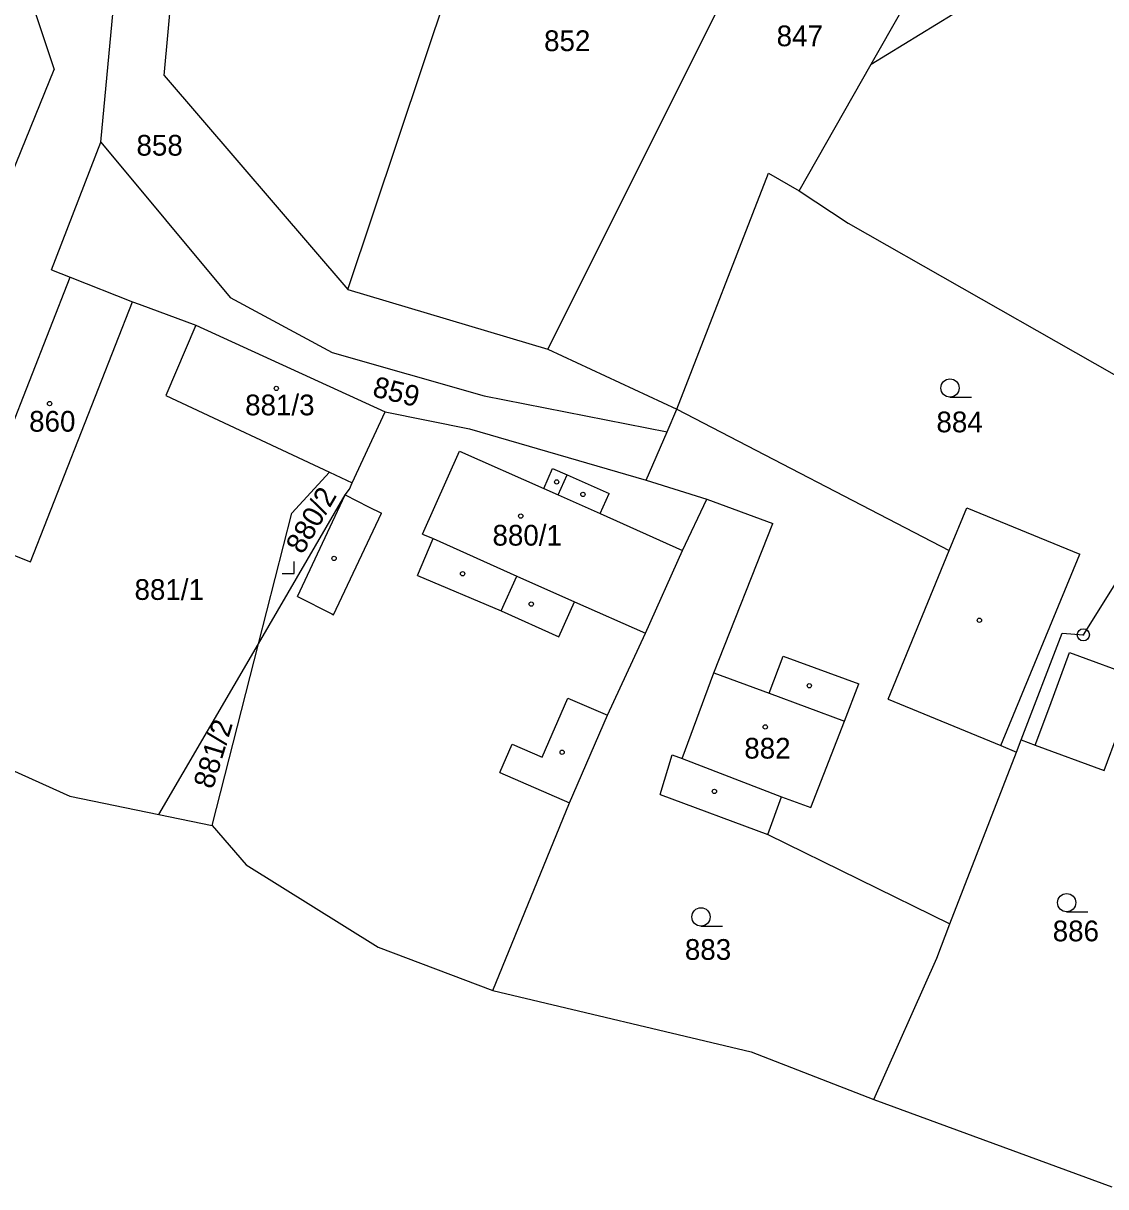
# Model space of a CAD drawing. Extents: x -779596 to -776743, y -1030330 to -1024513.
# Drawn here: x -777792.7 to -777704, y -1025546 to -1025450.6 of the extents above; entities that cross this region are included whole.
import ezdxf

# ---------------------------------------------------------------- set-up
doc = ezdxf.new("R2010")
doc.units = 0
for name, color, linetype in [('hranice parcel', 7, 'Continuous'), ('hranice vnitřní', 7, 'Continuous'), ('kultura', 7, 'Continuous'), ('Kód', 7, 'Continuous'), ('č_pacel stav_', 7, 'Continuous'), ('č_parcel poz_', 7, 'Continuous')]:
    doc.layers.add(name, color=color, linetype=linetype)

msp = doc.modelspace()

# ---------------------------------------------------------------- linework, layer by layer
at = {"layer": 'hranice parcel'}
for points in [[(-777786.38, -1025460.37), (-777782.85, -1025422.71)], [(-777766.12, -1025472.43), (-777751.71, -1025429.33)], [(-777781.19, -1025454.9), (-777779.17, -1025432.78)], [(-777723.23, -1025453.98), (-777712.96, -1025435.94)], [(-777723.23, -1025453.98), (-777697.79, -1025438.36)], [(-777793.53, -1025444.4), (-777790.21, -1025454.41)], [(-777749.74, -1025477.33), (-777735.37, -1025448.59)], [(-777729.14, -1025464.36), (-777723.23, -1025453.98)], [(-777809.88, -1025502.83), (-777790.21, -1025454.41)], [(-777781.19, -1025454.9), (-777766.12, -1025472.43)], [(-777790.42, -1025470.84), (-777786.38, -1025460.37)], [(-777786.38, -1025460.37), (-777775.78, -1025473.09)], [(-777739.17, -1025482.26), (-777731.64, -1025462.9)], [(-777731.64, -1025462.9), (-777729.14, -1025464.36)], [(-777729.14, -1025464.36), (-777725.11, -1025467.01)], [(-777725.11, -1025467.01), (-777697.17, -1025482.9)], [(-777790.42, -1025470.84), (-777788.88, -1025471.44)], [(-777797.26, -1025492.75), (-777788.88, -1025471.44)], [(-777788.88, -1025471.44), (-777783.77, -1025473.45)], [(-777775.78, -1025473.09), (-777767.4, -1025477.6)], [(-777766.12, -1025472.43), (-777749.74, -1025477.33)], [(-777792.15, -1025494.76), (-777783.77, -1025473.45)], [(-777783.77, -1025473.45), (-777783.24, -1025473.65)], [(-777783.24, -1025473.65), (-777778.58, -1025475.36)], [(-777778.58, -1025475.36), (-777781.04, -1025481.12)], [(-777778.58, -1025475.36), (-777763.08, -1025482.48)], [(-777767.4, -1025477.6), (-777754.95, -1025481.15)], [(-777749.74, -1025477.33), (-777739.17, -1025482.26)], [(-777781.04, -1025481.12), (-777767.62, -1025487.42)], [(-777754.95, -1025481.15), (-777739.96, -1025484.11)], [(-777765.76, -1025488.29), (-777763.08, -1025482.48)], [(-777763.08, -1025482.48), (-777756.16, -1025483.87)], [(-777739.96, -1025484.11), (-777739.17, -1025482.26)], [(-777739.17, -1025482.26), (-777716.84, -1025493.85)], [(-777756.16, -1025483.87), (-777741.67, -1025488.08)], [(-777741.67, -1025488.08), (-777739.96, -1025484.11)], [(-777770.72, -1025490.79), (-777767.62, -1025487.42)], [(-777767.62, -1025487.42), (-777765.76, -1025488.29)], [(-777705.84, -1025500.76), (-777697.43, -1025487.35)], [(-777765.99, -1025488.8), (-777765.76, -1025488.29)], [(-777741.67, -1025488.08), (-777736.7, -1025489.63)], [(-777773.45, -1025501.48), (-777766.34, -1025489.28)], [(-777766.34, -1025489.28), (-777765.99, -1025488.8)], [(-777738.69, -1025493.83), (-777736.7, -1025489.63)], [(-777736.7, -1025489.63), (-777731.3, -1025491.64)], [(-777716.84, -1025493.85), (-777715.39, -1025490.34)], [(-777715.39, -1025490.34), (-777706.13, -1025494.15)], [(-777773.45, -1025501.48), (-777770.72, -1025490.79)], [(-777736.13, -1025503.87), (-777731.3, -1025491.64)], [(-777797.26, -1025492.75), (-777792.15, -1025494.76)], [(-777741.72, -1025500.63), (-777738.69, -1025493.83)], [(-777712.6, -1025509.84), (-777706.13, -1025494.15)], [(-777744.84, -1025507.35), (-777741.72, -1025500.63)], [(-777710.95, -1025509.37), (-777707.57, -1025500.63)], [(-777707.57, -1025500.63), (-777705.84, -1025500.76)], [(-777781.61, -1025515.49), (-777773.45, -1025501.48)], [(-777777.25, -1025516.39), (-777773.45, -1025501.48)], [(-777708.6, -1025506.61), (-777706.97, -1025502.19)], [(-777706.97, -1025502.19), (-777701.31, -1025504.29)], [(-777738.73, -1025510.88), (-777736.13, -1025503.87)], [(-777709.78, -1025509.8), (-777708.6, -1025506.61)], [(-777747.95, -1025514.53), (-777744.84, -1025507.35)], [(-777711.33, -1025510.36), (-777710.95, -1025509.37)], [(-777710.95, -1025509.37), (-777709.78, -1025509.8)], [(-777797.12, -1025510.29), (-777788.92, -1025513.97)], [(-777716.78, -1025524.46), (-777711.33, -1025510.36)], [(-777712.6, -1025509.84), (-777711.33, -1025510.36)], [(-777740.52, -1025513.85), (-777739.54, -1025510.58)], [(-777739.54, -1025510.58), (-777738.73, -1025510.88)], [(-777788.92, -1025513.97), (-777781.61, -1025515.49)], [(-777740.52, -1025513.85), (-777731.71, -1025517.12)], [(-777754.23, -1025529.92), (-777747.95, -1025514.53)], [(-777781.61, -1025515.49), (-777777.25, -1025516.39)], [(-777777.25, -1025516.39), (-777774.45, -1025519.6)], [(-777731.71, -1025517.12), (-777716.78, -1025524.46)], [(-777774.45, -1025519.6), (-777763.64, -1025526.35)], [(-777717.86, -1025527.25), (-777716.78, -1025524.46)], [(-777763.64, -1025526.35), (-777754.23, -1025529.92)], [(-777723.01, -1025538.84), (-777717.86, -1025527.25)], [(-777754.23, -1025529.92), (-777733.06, -1025534.95)], [(-777733.06, -1025534.95), (-777723.01, -1025538.84)], [(-777723.01, -1025538.84), (-777703.5, -1025546)]]:
    msp.add_lwpolyline(points, dxfattribs=at)
at = {"layer": 'hranice vnitřní'}
for points in [[(-777760, -1025492.5), (-777756.97, -1025485.69)], [(-777756.97, -1025485.69), (-777750.07, -1025488.76)], [(-777750.07, -1025488.76), (-777749.34, -1025487.12)], [(-777749.34, -1025487.12), (-777748.15, -1025487.65)], [(-777748.88, -1025489.29), (-777748.15, -1025487.65)], [(-777748.15, -1025487.65), (-777744.72, -1025489.17)], [(-777770.26, -1025497.6), (-777766.34, -1025489.28)], [(-777766.34, -1025489.28), (-777764.44, -1025490.25)], [(-777750.07, -1025488.76), (-777748.88, -1025489.29)], [(-777748.88, -1025489.29), (-777745.45, -1025490.82)], [(-777745.45, -1025490.82), (-777744.72, -1025489.17)], [(-777764.44, -1025490.25), (-777763.38, -1025490.79)], [(-777767.29, -1025499.11), (-777763.38, -1025490.79)], [(-777745.45, -1025490.82), (-777738.69, -1025493.83)], [(-777760.41, -1025495.9), (-777759.13, -1025492.87)], [(-777760, -1025492.5), (-777759.13, -1025492.87)], [(-777759.13, -1025492.87), (-777752.28, -1025495.94)], [(-777721.85, -1025506.03), (-777716.84, -1025493.85)], [(-777760.41, -1025495.9), (-777753.56, -1025498.8)], [(-777753.56, -1025498.8), (-777752.28, -1025495.94)], [(-777752.28, -1025495.94), (-777747.55, -1025498.04)], [(-777770.26, -1025497.6), (-777767.44, -1025499.04)], [(-777748.83, -1025500.91), (-777747.55, -1025498.04)], [(-777747.55, -1025498.04), (-777741.72, -1025500.63)], [(-777767.44, -1025499.04), (-777767.29, -1025499.11)], [(-777753.56, -1025498.8), (-777748.83, -1025500.91)], [(-777731.6, -1025505.55), (-777730.44, -1025502.49)], [(-777730.44, -1025502.49), (-777724.23, -1025504.77)], [(-777736.13, -1025503.87), (-777731.6, -1025505.55)], [(-777725.43, -1025507.84), (-777724.23, -1025504.77)], [(-777731.6, -1025505.55), (-777725.43, -1025507.84)], [(-777750.2, -1025510.79), (-777748.1, -1025505.94)], [(-777748.1, -1025505.94), (-777744.84, -1025507.35)], [(-777721.85, -1025506.03), (-777712.6, -1025509.84)], [(-777728.18, -1025514.92), (-777725.43, -1025507.84)], [(-777704.13, -1025511.89), (-777702.95, -1025508.7)], [(-777753.68, -1025512.05), (-777752.67, -1025509.72)], [(-777752.67, -1025509.72), (-777750.2, -1025510.79)], [(-777709.78, -1025509.8), (-777704.13, -1025511.89)], [(-777738.73, -1025510.88), (-777730.58, -1025514.03)], [(-777753.68, -1025512.05), (-777747.95, -1025514.53)], [(-777731.71, -1025517.12), (-777730.58, -1025514.03)], [(-777730.58, -1025514.03), (-777728.18, -1025514.92)]]:
    msp.add_lwpolyline(points, dxfattribs=at)
at = {"layer": 'kultura'}
for points in [[(-777716.77, -1025481.27), (-777715.02, -1025481.27)], [(-777771.52, -1025495.73), (-777770.52, -1025495.73), (-777770.52, -1025494.73)], [(-777707.21, -1025523.46), (-777705.46, -1025523.46)], [(-777737.18, -1025524.63), (-777735.43, -1025524.63)]]:
    msp.add_lwpolyline(points, dxfattribs=at)
for centre, radius in [((-777716.77, -1025480.52), 0.75), ((-777771.99, -1025480.55), 0.175), ((-777790.57, -1025481.8), 0.175), ((-777749.01, -1025488.22), 0.175), ((-777746.86, -1025489.24), 0.175), ((-777751.95, -1025491.02), 0.175), ((-777767.25, -1025494.49), 0.175), ((-777756.72, -1025495.75), 0.175), ((-777751.09, -1025498.23), 0.175), ((-777714.36, -1025499.56), 0.175), ((-777728.3, -1025504.93), 0.175), ((-777731.91, -1025508.3), 0.175), ((-777748.56, -1025510.38), 0.175), ((-777736.08, -1025513.59), 0.175), ((-777707.21, -1025522.71), 0.75), ((-777737.18, -1025523.88), 0.75)]:
    msp.add_circle(centre, radius, dxfattribs=at)
at = {"layer": 'Kód'}
for radius in [0.5, 0.032]:
    msp.add_circle((-777705.84, -1025500.76), radius, dxfattribs=at)

# ---------------------------------------------------------------- texts
at = {"layer": 'č_pacel stav_'}
for s, p in [('881/3', (-777774.543, -1025482.76)), ('860', (-777792.249, -1025484.1)), ('880/1', (-777754.27, -1025493.44)), ('882', (-777733.63, -1025510.9))]:
    msp.add_text(s, height=1.7, dxfattribs=at).set_placement(p)
msp.add_text('880/2', height=1.7, rotation=59.80048, dxfattribs=at).set_placement((-777769.842, -1025494.227))
at = {"layer": 'č_parcel poz_'}
for s, p in [('852', (-777750.04, -1025452.9)), ('847', (-777730.98, -1025452.5)), ('858', (-777783.45, -1025461.47)), ('884', (-777717.88, -1025484.15)), ('881/1', (-777783.61, -1025497.89)), ('886', (-777708.35, -1025525.88)), ('883', (-777738.5, -1025527.4))]:
    msp.add_text(s, height=1.7, dxfattribs=at).set_placement(p)
for s, rotation, p in [('859', 346.10275, (-777764.188, -1025481.184)), ('881/2', 73.10058, (-777777.193, -1025513.471))]:
    msp.add_text(s, height=1.7, rotation=rotation, dxfattribs=at).set_placement(p)

doc.saveas('drawing.dxf')
